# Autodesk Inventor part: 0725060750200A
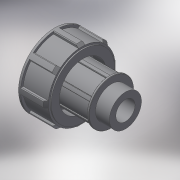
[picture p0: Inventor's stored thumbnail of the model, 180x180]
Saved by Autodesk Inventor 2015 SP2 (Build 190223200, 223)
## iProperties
Created: 2017-04
Part Number: 0725060750200A
Material: Generic
Description: PLASSON THREADED ADAPTOR 75-2"
Document SubType Name: Modeling
Designer: KIM
Density: 1 g/cm^3
Appearance: Default
Author: KIM
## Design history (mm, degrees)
derived "07250.ipt"
feature "Solid1::07250.ipt"
tag "TaggingFeature1"
body "Solid1"
other parameters: "d1" = 59.614, "d2" = 132, "d3" = 26, "d6" = 134, "d7" = 124.62, "d8" = 107.2, "d9" = 75, "d10" = 83.4596, "d12" = 35.7684, "d13" = 47.6912, "d14" = 29.9, "d15" = 100.5, "d16" = 3.96, "d17" = 52.8, "d18" = 26, "d19" = 31.2, "d24" = 11.9228, "d25" = 5.9614, "d27" = 0, "d28" = 4.76912, "d31" = 1.19228, "d35" = 360 deg, "d41" = 29.337, "d56" = 78.75, "d57" = 7.5, "d58" = 3.75, "d60" = 0, "d61" = 0.59614, "d64" = 0.59614, "d68" = 360 deg, "d_" = 75, "R_" = 59.614, "E_" = 134, "H_" = 132, "l_2" = 26, "d55" = 75
